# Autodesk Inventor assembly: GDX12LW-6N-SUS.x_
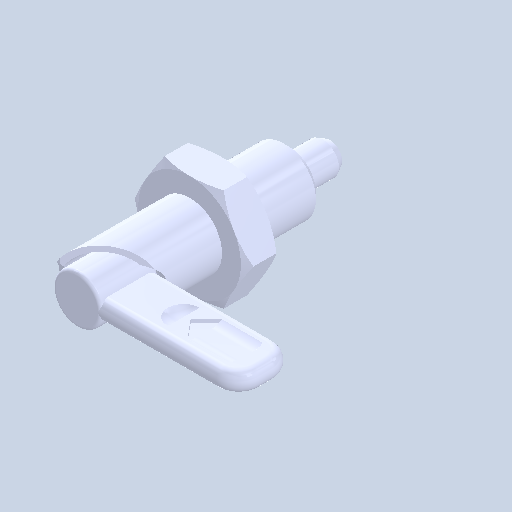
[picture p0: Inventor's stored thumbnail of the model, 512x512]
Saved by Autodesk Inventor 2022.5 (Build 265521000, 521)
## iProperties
Created: 2024-06
Part Number: GDX12LW-6N-SUS.x_
Document SubType Name: Assembly
Designer: ImaoCorp
Author: ImaoCorp
Sending System: SOLIDWORKS 2022-2022290
MC: AMD64
MC_MODEL: Intel64 Family 6 Model 60 Stepping 3, GenuineIntel
OS: Windows_NT
FRU: Parasolid Version 33.1, build 260,  4-25-2022
FORMAT: text
GUISE: transmit
KEY: FILEGDX12LW-6N-SUS.x_t
DATE: Wed Jun 12 09:32:04 2024
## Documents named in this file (4)
- Y:\5.更新分\2024年対応\xxxx_GDX\データ_imao品番\gdx12lw-6n-sus\GDX12LW-6N-SUS.x_.iam
- Y:\5.更新分\2024年対応\xxxx_GDX\データ_imao品番\gdx12lw-6n-sus\GDX12LW-6N-SUS_01.ipt
- Y:\5.更新分\2024年対応\xxxx_GDX\データ_imao品番\gdx12lw-6n-sus\GDX12LW-6N-SUS_02.ipt
- Y:\5.更新分\2024年対応\xxxx_GDX\データ_imao品番\gdx12lw-6n-sus\GDX12LW-6N-SUS_03.ipt
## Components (3 placed, 3 different names)
1. GDX12LW-6N-SUS_01
2. GDX12LW-6N-SUS_02
3. GDX12LW-6N-SUS_03
